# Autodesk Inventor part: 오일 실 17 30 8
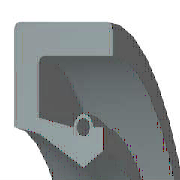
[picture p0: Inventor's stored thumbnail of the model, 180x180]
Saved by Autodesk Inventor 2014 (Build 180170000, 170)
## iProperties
Created: 2012-02
Part Number: 오일 실 17 30 8
Material: 고무
Description: 오일-실
Document SubType Name: Modeling
Standard: KS B 2804
Designer: mduedu
Standards Organization: KS
Language: ko-KR
Size Designation: S - 17 30 8
Categories: <MemberInstance><Categories><Category DisplayName="샤프트 부품" InternalName="7f7aeb1f-a693-4053-b835-cee3144e0d98" Mnemonic="SHFT"><Category DisplayName="실링" Intern
Density: 0.93 g/cm^3
Appearance: 고무 - 검은색 - 버전 1.1
IsCustomPart: 1
Author: mduedu
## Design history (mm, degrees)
revolve "본체" stored, may be unused: angle "d17" = 90 deg
revolve "스프링1" stored, may be unused: angle "d18" = 90 deg
body "Solid1"
sketch "스케치1"
  geometry: L1 (0, 15)-(8, 15); L2 (8, 15)-(8, 13.75); L3 (8, 13.75)-(1.75, 13.75); L4 (0, 15)-(0, 10.6); L5 (0, 10.6)-(1.75, 10.25); L6 (1.75, 10.25)-(4.9, 8.5); L7 (4.9, 8.5)-(0, 8.5); L8 (6.3, 9.375)-(6.3, 10.6); L9 (0, 0)-(9.586, 0) reference; L10 (4.9, 8.5)-(6.3, 9.375); L11 (0, 18)-(0, -3) reference; L12 (-1.917, 0)-(11.503, 0) reference; L13 (4.2, 10.6)-(1.75, 11.09); L14 (1.75, 11.09)-(1.75, 13.75); L15 (6.3, 10.6)-(5.6, 10.6); C1 r 0.455 at (4.9, 10.6); A1 r 0.7 centre (4.9, 10.6) between (5.6, 10.6) and (4.2, 10.6)
  constraints: 26 end point, 5 horizontal alignment, 4 perpendicular, 2 centre point, 2 collinear, 2 horizontal, 2 parallel, 2 point on circle, 2 point on line, 2 vertical alignment, 1 coincident
  dimensions: "d0" = 30 diameter of L1 L9 (= SD2); "d1" = 18.75 diameter of L8.start L9 (= ABDM); "d2" = 1.25 distance of L1.end L2.end (computed from SD); "d3" = 0.91 diameter of C1 (= SPDI); "d4" = 1.4 diameter of A1 (= SPDA); "d5" = 17 diameter of L6.end L9 (= NND); "d6" = 20.5 diameter of L5.end L9 (= TKDM); "d7" = 21.2 diameter of L4.end L9 (= HLDM); "d8" = 4.9 distance from line of C1.centre L4 (= SPDST); "d9" = 6.3 distance between parallel lines of L8 L4 (= SDI); "d10" = 8 distance between parallel lines of L2 L4 (= SWDT); "d12" = 1.75 distance between parallel lines of L14 L4 (= SD)
fillet "모깎기1" dims "d11" = 0.3 (= RR)
other parameters: "SD2" = 30 [user parameter; used in 1 equation term], "SWDT" = 8 [user parameter; used in 1 equation term], "RR" = 0.3 [user parameter; used in 1 equation term], "SD" = 1.75 [user parameter; used in 2 equation terms], "NND" = 17 [user parameter; used in 1 equation term], "SPDA" = 1.4 [user parameter; used in 1 equation term], "SPDI" = 0.91 [user parameter; used in 1 equation term], "TKDM" = 20.5 [user parameter; used in 1 equation term], "HLDM" = 21.2 [user parameter; used in 1 equation term], "ABDM" = 18.75 [user parameter; used in 1 equation term], "SDI" = 6.3 [user parameter; used in 1 equation term], "SPDST" = 4.9 [user parameter; used in 1 equation term], "d13" = 0, "d14" = 0, "d15" = 0, "LAB" = 0.35 [user parameter]
